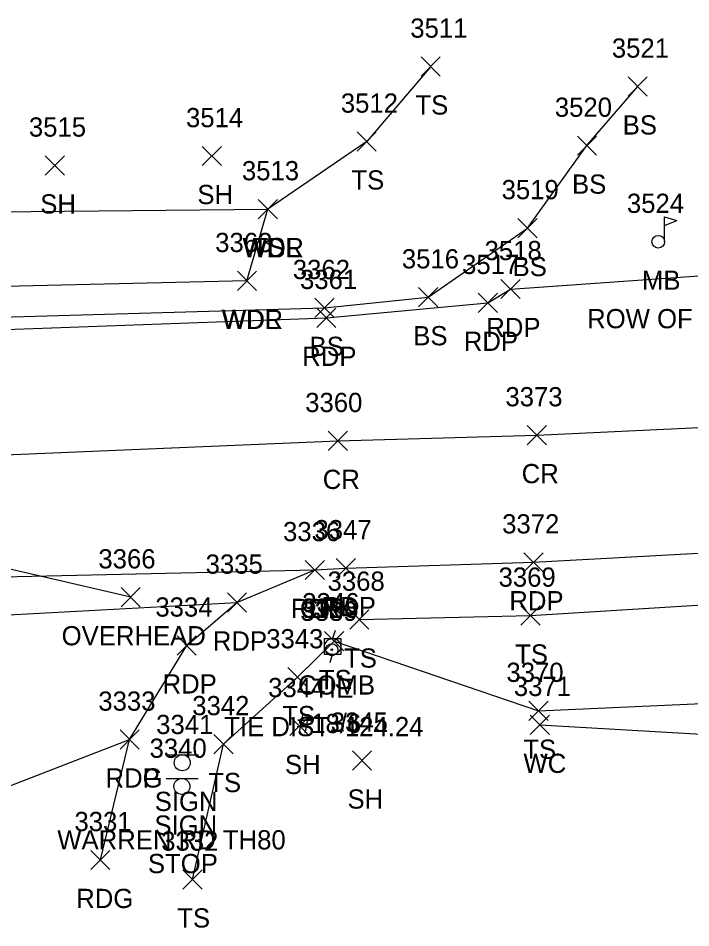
# Model space of a CAD drawing. Extents: x 1611797 to 1633212, y 298978 to 305475.
# Drawn here: x 1617252.1 to 1617322.1, y 301419.2 to 301513.8 of the extents above; entities that cross this region are included whole.
import ezdxf

# ---------------------------------------------------------------- set-up
doc = ezdxf.new("R2010")
doc.units = 0
for name, color, linetype in [('C_A', 7, 'Continuous'), ('C_C', 7, 'Continuous'), ('C_I', 7, 'Continuous'), ('CBP', 7, 'Continuous'), ('L_A', 7, 'Continuous'), ('L_C', 7, 'Continuous'), ('L_I', 7, 'Continuous'), ('L_TIC', 7, 'Continuous'), ('LAWA', 7, 'Continuous'), ('LAWE', 7, 'Continuous'), ('LELB', 7, 'Continuous'), ('LMB', 7, 'Continuous'), ('P_A', 7, 'Continuous'), ('P_I', 7, 'Continuous'), ('P_TIC', 7, 'Continuous'), ('PET', 7, 'Continuous'), ('PEU', 7, 'Continuous'), ('PRC', 7, 'Continuous'), ('S_A', 7, 'Continuous'), ('S_C', 7, 'Continuous'), ('S_I', 7, 'Continuous'), ('SSGN', 7, 'Continuous'), ('U_A', 7, 'Continuous'), ('U_C', 7, 'Continuous'), ('U_I', 7, 'Continuous'), ('U_TIC', 7, 'Continuous'), ('UCO', 7, 'Continuous'), ('UP', 7, 'Continuous')]:
    doc.layers.add(name, color=color, linetype=linetype)

msp = doc.modelspace()

# ---------------------------------------------------------------- linework, layer by layer
at = {"layer": 'CBP'}
for radius in [0.625, 0.0833]:
    msp.add_circle((1617284.76, 301448.09), radius, dxfattribs=at)
at = {"layer": 'L_TIC'}
for points in [[(1617294.052, 301507.764), (1617296.052, 301509.764)], [(1617296.052, 301507.764), (1617294.052, 301509.764)], [(1617315.595, 301505.687), (1617317.595, 301507.687)], [(1617317.595, 301505.687), (1617315.595, 301507.687)], [(1617287.39, 301499.963), (1617289.39, 301501.963)], [(1617289.39, 301499.963), (1617287.39, 301501.963)], [(1617310.316, 301499.534), (1617312.316, 301501.534)], [(1617312.316, 301499.534), (1617310.316, 301501.534)], [(1617271.278, 301498.451), (1617273.278, 301500.451)], [(1617273.278, 301498.451), (1617271.278, 301500.451)], [(1617254.927, 301497.472), (1617256.927, 301499.472)], [(1617256.927, 301497.472), (1617254.927, 301499.472)], [(1617277.097, 301492.929), (1617279.097, 301494.929)], [(1617279.097, 301492.929), (1617277.097, 301494.929)], [(1617277.097, 301492.929), (1617279.097, 301494.929)], [(1617279.097, 301492.929), (1617277.097, 301494.929)], [(1617277.097, 301492.929), (1617279.097, 301494.929)], [(1617279.097, 301492.929), (1617277.097, 301494.929)], [(1617304.131, 301490.958), (1617306.131, 301492.958)], [(1617306.131, 301490.958), (1617304.131, 301492.958)], [(1617274.931, 301485.459), (1617276.931, 301487.459)], [(1617276.931, 301485.459), (1617274.931, 301487.459)], [(1617274.931, 301485.459), (1617276.931, 301487.459)], [(1617276.931, 301485.459), (1617274.931, 301487.459)], [(1617293.799, 301483.761), (1617295.799, 301485.761)], [(1617295.799, 301483.761), (1617293.799, 301485.761)], [(1617283.009, 301482.653), (1617285.009, 301484.653)], [(1617285.009, 301482.653), (1617283.009, 301484.653)], [(1617286.625, 301450.225), (1617288.625, 301452.225)], [(1617288.625, 301450.225), (1617286.625, 301452.225)], [(1617304.43, 301450.647), (1617306.43, 301452.647)], [(1617306.43, 301450.647), (1617304.43, 301452.647)], [(1617283.996, 301447.984), (1617285.996, 301449.984)], [(1617285.996, 301447.984), (1617283.996, 301449.984)], [(1617280.194, 301444.236), (1617282.194, 301446.236)], [(1617282.194, 301444.236), (1617280.194, 301446.236)], [(1617305.277, 301440.74), (1617307.277, 301442.74)], [(1617307.277, 301440.74), (1617305.277, 301442.74)], [(1617280.392, 301439.154), (1617282.392, 301441.154)], [(1617282.392, 301439.154), (1617280.392, 301441.154)], [(1617305.4, 301439.273), (1617307.4, 301441.273)], [(1617307.4, 301439.273), (1617305.4, 301441.273)], [(1617272.493, 301437.275), (1617274.493, 301439.275)], [(1617274.493, 301437.275), (1617272.493, 301439.275)], [(1617286.907, 301435.56), (1617288.907, 301437.56)], [(1617288.907, 301435.56), (1617286.907, 301437.56)], [(1617269.265, 301423.187), (1617271.265, 301425.187)], [(1617271.265, 301423.187), (1617269.265, 301425.187)]]:
    msp.add_lwpolyline(points, dxfattribs=at)
at = {"layer": 'LAWA'}
for points in [[(1617275.931, 301486.459), (1617240.325, 301485.625), (1617239.298, 301493.531), (1617278.097, 301493.929)], [(1617275.931, 301486.459), (1617278.097, 301493.929)]]:
    msp.add_lwpolyline(points, dxfattribs=at)
at = {"layer": 'LAWE'}
msp.add_lwpolyline([(1617306.4, 301440.273), (1617351.456, 301437.682), (1617369.768, 301453.806), (1617393.242, 301457.251), (1617436.552, 301457.26), (1617474.538, 301459.197), (1617502.738, 301461.103), (1617532.404, 301457.711), (1617564.246, 301457.252), (1617611.499, 301454.941), (1617640.602, 301457.223), (1617646.966, 301460.46), (1617651.498, 301460.169)], dxfattribs=at)
at = {"layer": 'LELB'}
for points in [[(1617295.052, 301508.764), (1617288.39, 301500.963), (1617278.097, 301493.929)], [(1617112.075, 301486.891), (1617143.187, 301485.899), (1617160.382, 301485.627), (1617168.744, 301490.478), (1617181.827, 301488.902), (1617182.981, 301485.132), (1617185.087, 301483.27), (1617185.155, 301482.484), (1617228.645, 301482.215), (1617247.861, 301482.609), (1617284.009, 301483.653), (1617294.799, 301484.761), (1617305.131, 301491.958), (1617311.316, 301500.534), (1617316.595, 301506.687)], [(1617270.265, 301424.187), (1617273.493, 301438.275), (1617281.194, 301445.236), (1617284.996, 301448.984), (1617306.277, 301441.74), (1617351.117, 301443.742), (1617369.915, 301458.224)], [(1617287.625, 301451.225), (1617305.43, 301451.647), (1617349.077, 301454.364), (1617369.915, 301458.224)]]:
    msp.add_lwpolyline(points, dxfattribs=at)
at = {"layer": 'LMB'}
for p, q in [((1617319.381, 301493.137), (1617320.675, 301492.755)), ((1617319.387, 301490.545), (1617319.386, 301493.139)), ((1617319.386, 301492.238), (1617320.669, 301492.746)), ((1617318.731, 301490.536), (1617318.731, 301490.536))]:
    msp.add_line(p, q, dxfattribs=at)
msp.add_circle((1617318.731, 301490.536), 0.656, dxfattribs=at)
at = {"layer": 'P_TIC'}
for points in [[(1617302.35, 301484.619), (1617304.35, 301486.619)], [(1617304.35, 301484.619), (1617302.35, 301486.619)], [(1617300.008, 301483.18), (1617302.008, 301485.18)], [(1617302.008, 301483.18), (1617300.008, 301485.18)], [(1617283.193, 301481.618), (1617285.193, 301483.618)], [(1617285.193, 301481.618), (1617283.193, 301483.618)], [(1617284.384, 301468.816), (1617286.384, 301470.816)], [(1617286.384, 301468.816), (1617284.384, 301470.816)], [(1617305.087, 301469.414), (1617307.087, 301471.414)], [(1617307.087, 301469.414), (1617305.087, 301471.414)], [(1617285.212, 301455.581), (1617287.212, 301457.581)], [(1617287.212, 301455.581), (1617285.212, 301457.581)], [(1617304.747, 301456.187), (1617306.747, 301458.187)], [(1617306.747, 301456.187), (1617304.747, 301458.187)], [(1617282, 301455.385), (1617284, 301457.385)], [(1617284, 301455.385), (1617282, 301457.385)], [(1617282, 301455.385), (1617284, 301457.385)], [(1617284, 301455.385), (1617282, 301457.385)], [(1617273.89, 301452.002), (1617275.89, 301454.002)], [(1617275.89, 301452.002), (1617273.89, 301454.002)], [(1617273.89, 301452.002), (1617275.89, 301454.002)], [(1617275.89, 301452.002), (1617273.89, 301454.002)], [(1617268.658, 301447.534), (1617270.658, 301449.534)], [(1617270.658, 301447.534), (1617268.658, 301449.534)], [(1617262.72, 301437.747), (1617264.72, 301439.747)], [(1617264.72, 301437.747), (1617262.72, 301439.747)], [(1617262.72, 301437.747), (1617264.72, 301439.747)], [(1617264.72, 301437.747), (1617262.72, 301439.747)], [(1617259.67, 301425.217), (1617261.67, 301427.217)], [(1617261.67, 301425.217), (1617259.67, 301427.217)]]:
    msp.add_lwpolyline(points, dxfattribs=at)
at = {"layer": 'PET'}
for points in [[(1616800.245, 301498.655), (1616846.202, 301496.41), (1616877.66, 301494.987), (1616924.574, 301492.623), (1616970.468, 301491.049), (1617010.053, 301488.605), (1617057.186, 301485.96), (1617084.655, 301484.653), (1617112.231, 301483.269), (1617143.255, 301482.016), (1617179.273, 301481.283), (1617228.989, 301480.95), (1617247.91, 301481.3), (1617284.193, 301482.618), (1617301.008, 301484.18), (1617303.35, 301485.619), (1617332.28, 301487.641)], [(1616797.897, 301472.147), (1616833.557, 301469.26), (1616835.781, 301467.097), (1616855.944, 301466.362), (1616855.748, 301466.314), (1616873.584, 301465.441), (1616877.417, 301468.148), (1616897.069, 301467.674), (1616949.801, 301465.546), (1616981.324, 301463.655), (1617031.568, 301460.574), (1617078.637, 301458.308), (1617107.825, 301456.691), (1617115.475, 301456.049), (1617116.766, 301454.339), (1617148.537, 301452.931), (1617180.448, 301452.693), (1617221.947, 301452.442), (1617236.35, 301450.911), (1617274.89, 301453.002), (1617283, 301456.385), (1617286.212, 301456.581), (1617305.747, 301457.187), (1617347.142, 301459.437)], [(1617236.35, 301450.911), (1617241.815, 301445.37), (1617246.224, 301432.004), (1617263.72, 301438.747), (1617269.658, 301448.534), (1617274.89, 301453.002)]]:
    msp.add_lwpolyline(points, dxfattribs=at)
at = {"layer": 'PEU'}
msp.add_lwpolyline([(1617260.67, 301426.217), (1617263.72, 301438.747)], dxfattribs=at)
at = {"layer": 'PRC'}
for points in [[(1616799.189, 301484.56), (1616831.113, 301483.228), (1616876.685, 301481.736), (1616923.02, 301479.203), (1616971.217, 301476.623), (1617010.298, 301474.423), (1617055.253, 301471.912), (1617111.198, 301469.473), (1617142.645, 301468.198), (1617179.739, 301467.038), (1617184.952, 301467.254), (1617234.042, 301467.951), (1617248.258, 301468.249), (1617285.384, 301469.816), (1617306.087, 301470.414), (1617345.061, 301472.238)], [(1617121.051, 301456.694), (1617148.105, 301456.153), (1617180.527, 301455.168), (1617222.547, 301455.051), (1617283, 301456.385)]]:
    msp.add_lwpolyline(points, dxfattribs=at)
at = {"layer": 'SSGN'}
for p, q in [((1617267.546, 301437.167), (1617270.879, 301437.167)), ((1617269.193, 301436.334), (1617269.193, 301436.334)), ((1617267.513, 301434.699), (1617270.847, 301434.699)), ((1617269.16, 301433.866), (1617269.16, 301433.866))]:
    msp.add_line(p, q, dxfattribs=at)
for centre in [(1617269.193, 301436.334), (1617269.16, 301433.866)]:
    msp.add_circle(centre, 0.833, dxfattribs=at)
at = {"layer": 'U_TIC'}
for points in [[(1617262.83, 301452.549), (1617264.83, 301454.549)], [(1617264.83, 301452.549), (1617262.83, 301454.549)]]:
    msp.add_lwpolyline(points, dxfattribs=at)
at = {"layer": 'UCO'}
msp.add_lwpolyline([(1617263.83, 301453.549), (1617140.319, 301482.181)], dxfattribs=at)
at = {"layer": 'UP'}
for p, q in [((1617285.099, 301450.089), (1617284.849, 301449.256)), ((1617284.016, 301447.589), (1617284.016, 301449.256)), ((1617284.016, 301449.256), (1617285.682, 301449.256)), ((1617285.682, 301449.256), (1617285.682, 301447.589)), ((1617284.849, 301448.423), (1617284.849, 301448.423)), ((1617285.682, 301447.589), (1617284.016, 301447.589)), ((1617284.599, 301446.756), (1617284.849, 301447.589))]:
    msp.add_line(p, q, dxfattribs=at)
msp.add_circle((1617284.849, 301448.423), 0.833, dxfattribs=at)

# ---------------------------------------------------------------- texts
at = {"layer": 'C_A'}
msp.add_text('TIE', height=2, dxfattribs=at).set_placement((1617282.839, 301443.09))
at = {"layer": 'C_C'}
msp.add_text('TIE DIST=124.24', height=2, dxfattribs=at).set_placement((1617273.564, 301439.09))
at = {"layer": 'C_I'}
msp.add_text('3339', height=2, dxfattribs=at).set_placement((1617281.492, 301451.09))
at = {"layer": 'L_A'}
for s, p in [('TS', (1617293.462, 301503.764)), ('BS', (1617315.036, 301501.687)), ('TS', (1617286.8, 301495.963)), ('BS', (1617309.757, 301495.534)), ('SH', (1617270.766, 301494.451)), ('SH', (1617254.416, 301493.472)), ('WDR', (1617275.459, 301488.929)), ('WDL', (1617275.514, 301488.929)), ('TS', (1617276.506, 301488.929)), ('BS', (1617303.572, 301486.958)), ('MB', (1617317.039, 301485.536)), ('WDR', (1617273.293, 301481.459)), ('WDL', (1617273.348, 301481.459)), ('BS', (1617293.24, 301479.761)), ('BS', (1617282.45, 301478.653)), ('TS', (1617286.035, 301446.225)), ('TS', (1617303.839, 301446.647)), ('TS', (1617283.406, 301443.984)), ('TS', (1617279.603, 301440.236)), ('TS', (1617304.686, 301436.74)), ('SH', (1617279.88, 301435.154)), ('WC', (1617304.707, 301435.273)), ('TS', (1617271.903, 301433.275)), ('SH', (1617286.395, 301431.56)), ('TS', (1617268.675, 301419.187))]:
    msp.add_text(s, height=2, dxfattribs=at).set_placement(p)
at = {"layer": 'L_C'}
msp.add_text('ROW OF 4', height=2, dxfattribs=at).set_placement((1617311.33, 301481.536))
at = {"layer": 'L_I'}
for s, p in [('3511', (1617292.926, 301511.764)), ('3521', (1617313.903, 301509.687)), ('3512', (1617285.698, 301503.963)), ('3520', (1617307.97, 301503.534)), ('3514', (1617269.585, 301502.451)), ('3515', (1617253.235, 301501.472)), ('3513', (1617275.404, 301496.929)), ('3513', (1617275.404, 301496.929)), ('3513', (1617275.404, 301496.929)), ('3519', (1617302.431, 301494.958)), ('3524', (1617315.472, 301493.536)), ('3363', (1617272.624, 301489.459)), ('3363', (1617272.624, 301489.459)), ('3516', (1617292.051, 301487.761)), ('3362', (1617280.702, 301486.653)), ('3369', (1617302.115, 301454.647)), ('3368', (1617284.318, 301454.225)), ('3346', (1617281.682, 301451.984)), ('3343', (1617277.934, 301448.236)), ('3370', (1617302.931, 301444.74)), ('3344', (1617278.132, 301443.154)), ('3371', (1617303.707, 301443.273)), ('3342', (1617270.233, 301441.275)), ('3345', (1617284.647, 301439.56)), ('3332', (1617267.006, 301427.187))]:
    msp.add_text(s, height=2, dxfattribs=at).set_placement(p)
at = {"layer": 'P_A'}
for s, p in [('RDP', (1617300.838, 301480.619)), ('RDP', (1617298.496, 301479.18)), ('RDP', (1617281.681, 301477.618)), ('CR', (1617304.52, 301465.414)), ('CR', (1617283.817, 301464.816)), ('RDP', (1617303.235, 301452.187)), ('RDP', (1617280.488, 301451.385)), ('CR', (1617281.433, 301451.385)), ('RDP', (1617283.7, 301451.581)), ('RDP', (1617272.378, 301448.002)), ('RDP', (1617272.378, 301448.002)), ('RDP', (1617267.146, 301443.534)), ('RDG', (1617261.208, 301433.747)), ('RDP', (1617261.208, 301433.747)), ('RDG', (1617258.158, 301421.217))]:
    msp.add_text(s, height=2, dxfattribs=at).set_placement(p)
at = {"layer": 'P_I'}
for s, p in [('3518', (1617300.658, 301488.619)), ('3517', (1617298.315, 301487.18)), ('3361', (1617281.453, 301485.618)), ('3373', (1617302.828, 301473.414)), ('3360', (1617281.991, 301472.816)), ('3372', (1617302.488, 301460.187)), ('3336', (1617279.685, 301459.385)), ('3336', (1617279.685, 301459.385)), ('3347', (1617282.952, 301459.581)), ('3335', (1617271.63, 301456.002)), ('3335', (1617271.63, 301456.002)), ('3334', (1617266.398, 301451.534)), ('3333', (1617260.46, 301441.747)), ('3333', (1617260.46, 301441.747)), ('3331', (1617257.977, 301429.217))]:
    msp.add_text(s, height=2, dxfattribs=at).set_placement(p)
at = {"layer": 'S_A'}
for p in [(1617266.331, 301431.313), (1617266.298, 301428.845)]:
    msp.add_text('SIGN', height=2, dxfattribs=at).set_placement(p)
at = {"layer": 'S_C'}
for s, p in [('WARREN RD TH80', (1617256.189, 301427.313)), ('STOP', (1617265.621, 301424.845))]:
    msp.add_text(s, height=2, dxfattribs=at).set_placement(p)
at = {"layer": 'S_I'}
for s, p in [('3341', (1617266.48, 301439.313)), ('3340', (1617265.794, 301436.845))]:
    msp.add_text(s, height=2, dxfattribs=at).set_placement(p)
at = {"layer": 'U_A'}
for s, p in [('OVERHEAD', (1617256.642, 301448.549)), ('COMB', (1617281.235, 301443.423))]:
    msp.add_text(s, height=2, dxfattribs=at).set_placement(p)
at = {"layer": 'U_C'}
msp.add_text('#18/6', height=2, dxfattribs=at).set_placement((1617281.125, 301439.423))
at = {"layer": 'U_I'}
for s, p in [('3366', (1617260.468, 301456.549)), ('3338', (1617281.589, 301451.423))]:
    msp.add_text(s, height=2, dxfattribs=at).set_placement(p)

doc.saveas('drawing.dxf')
